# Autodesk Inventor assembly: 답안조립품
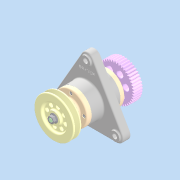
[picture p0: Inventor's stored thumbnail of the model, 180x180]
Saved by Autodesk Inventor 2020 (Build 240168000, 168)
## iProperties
Created: 2023-04
Part Number: 답안조립품
Document SubType Name: Assembly
Designer: oem
Author: oem
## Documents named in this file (11)
- C:\Users\oem\Desktop\730407V1021\답안조립품.iam
- C:\Users\oem\Desktop\730407V1021\본체.ipt
- C:\Users\oem\Desktop\730407V1021\축.ipt
- C:\Users\oem\Desktop\730407V1021\오일 실 20 32 8.ipt
- C:\Users\oem\Desktop\730407V1021\커버.ipt
- C:\Users\oem\Desktop\730407V1021\베어링 6204.ipt
- C:\Users\oem\Desktop\730407V1021\묻힘키 5x5x16.ipt
- C:\Users\oem\Desktop\730407V1021\스퍼기어.ipt
- C:\Users\oem\Desktop\730407V1021\6각 플랜지 너트 M10.ipt
- C:\Users\oem\Desktop\730407V1021\볼트 M4 x 12.ipt
- C:\Users\oem\Desktop\730407V1021\v-벨트풀리.ipt
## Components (3 placed, 2 different names)
1. 6각 플랜지 너트 M10:1 — 각도:4
2. v-벨트풀리:1 — 각도:8
3. 6각 플랜지 너트 M10:2 — 각도:9
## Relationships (3: Angle 3)
- 각도:4 [Angle]: 6각 플랜지 너트 M10:1
- 각도:8 [Angle]: v-벨트풀리:1
- 각도:9 [Angle]: 6각 플랜지 너트 M10:2
